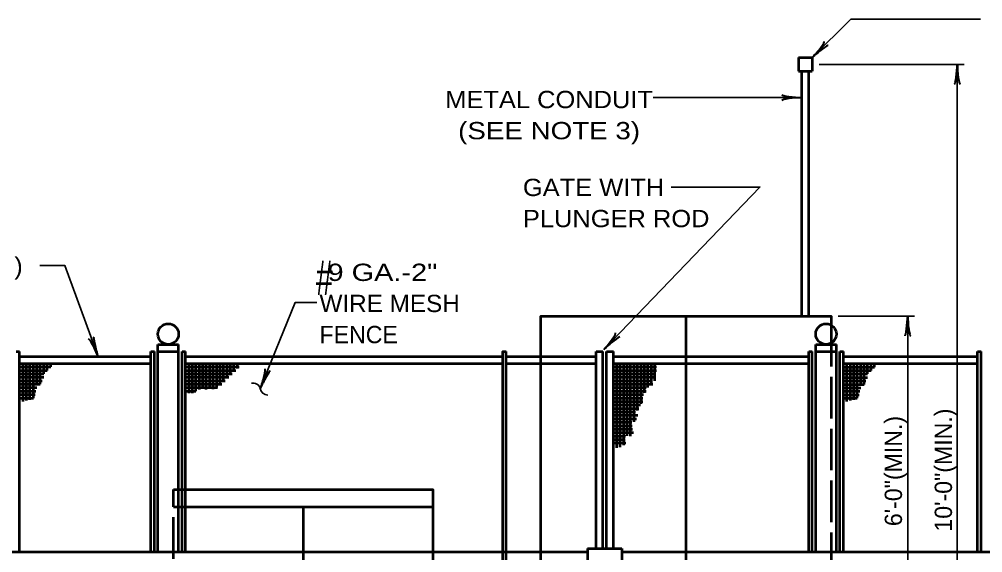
# Model space of a CAD drawing. Extents: x -1 to 679, y 0 to 440.
# Drawn here: x 122.8 to 262.1, y 140.7 to 217.9 of the extents above; entities that cross this region are included whole.
import ezdxf
from ezdxf.enums import TextEntityAlignment as Align

# ---------------------------------------------------------------- set-up
doc = ezdxf.new("R2010")
doc.units = 0
doc.linetypes.add('LONG_DASHED', pattern=[7.5, 6, -1.5])
doc.layers.add('1', color=7, linetype='Continuous', lineweight=53)

msp = doc.modelspace()

# ---------------------------------------------------------------- linework, layer by layer
at = {"layer": '1'}
for p, q in [((235.447, 212.358), (237.447, 212.358)), ((235.447, 212.358), (235.447, 210.358)), ((237.447, 212.358), (237.447, 210.358)), ((235.447, 210.358), (237.447, 210.358)), ((235.947, 174.962), (235.947, 210.358)), ((236.947, 174.962), (236.947, 210.358)), ((219.197, 174.962), (219.197, 109.858)), ((142.849, 170.858), (145.849, 170.858)), ((142.849, 140.858), (142.849, 170.858)), ((145.849, 140.858), (145.849, 170.858)), ((237.947, 170.858), (240.947, 170.858)), ((237.947, 140.858), (237.947, 170.858)), ((240.947, 140.858), (240.947, 170.858)), ((122.349, 169.858), (122.849, 169.858)), ((122.849, 140.858), (122.849, 169.858)), ((122.849, 169.108), (141.849, 169.108)), ((141.849, 169.858), (142.349, 169.858)), ((141.849, 140.858), (141.849, 169.858)), ((142.349, 140.858), (142.349, 169.858)), ((142.849, 169.858), (145.849, 169.858)), ((146.349, 169.858), (146.849, 169.858)), ((146.349, 140.858), (146.349, 169.858)), ((146.849, 140.858), (146.849, 169.858)), ((146.849, 169.108), (192.697, 169.108)), ((193.197, 108.858), (193.197, 169.858)), ((193.197, 169.108), (206.197, 169.108)), ((206.197, 169.858), (207.197, 169.858)), ((206.197, 141.358), (206.197, 169.858)), ((207.197, 141.358), (207.197, 169.858)), ((207.697, 169.858), (208.697, 169.858)), ((207.697, 141.358), (207.697, 169.858)), ((208.697, 141.358), (208.697, 169.858)), ((208.697, 169.108), (236.947, 169.108)), ((236.947, 169.858), (237.447, 169.858)), ((236.947, 140.858), (236.947, 169.858)), ((237.447, 140.858), (237.447, 169.858)), ((237.947, 169.858), (240.947, 169.858)), ((241.447, 169.858), (241.947, 169.858)), ((241.447, 140.858), (241.447, 169.858)), ((241.947, 140.858), (241.947, 169.858)), ((241.947, 169.108), (261.349, 169.108)), ((261.349, 140.858), (261.349, 169.858)), ((261.349, 169.858), (261.849, 169.858)), ((261.849, 140.858), (261.849, 169.858)), ((122.849, 168.108), (141.849, 168.108)), ((122.849, 167.608), (127.349, 167.608)), ((123.349, 162.608), (123.349, 168.108)), ((123.849, 162.758), (123.849, 168.108)), ((124.349, 162.858), (124.349, 168.108)), ((124.849, 163.108), (124.849, 168.108)), ((125.349, 165.108), (125.349, 168.108)), ((125.849, 165.108), (125.849, 168.108)), ((126.349, 166.608), (126.349, 168.108)), ((126.849, 167.108), (126.849, 168.108)), ((127.349, 167.608), (127.349, 168.108)), ((146.849, 168.108), (192.697, 168.108)), ((146.849, 167.608), (154.599, 167.608)), ((147.349, 163.79), (147.349, 168.108)), ((147.849, 163.817), (147.849, 168.108)), ((148.349, 164.108), (148.349, 168.108)), ((148.849, 164.332), (148.849, 168.108)), ((149.349, 164.413), (149.349, 168.108)), ((149.849, 164.359), (149.849, 168.108)), ((150.349, 164.413), (150.349, 168.108)), ((150.849, 164.386), (150.849, 168.108)), ((151.349, 164.608), (151.349, 168.108)), ((151.849, 165.108), (151.849, 168.108)), ((152.349, 165.608), (152.349, 168.108)), ((152.849, 165.93), (152.849, 168.108)), ((153.349, 166.498), (153.349, 168.108)), ((153.849, 167.013), (153.849, 168.108)), ((154.349, 167.358), (154.349, 168.108)), ((193.197, 168.108), (206.197, 168.108)), ((208.697, 168.108), (236.947, 168.108)), ((208.697, 167.608), (214.919, 167.608)), ((209.197, 155.917), (209.197, 168.108)), ((209.697, 156.002), (209.697, 168.108)), ((210.197, 156.282), (210.197, 168.108)), ((210.697, 157.655), (210.697, 168.108)), ((211.197, 157.612), (211.197, 168.108)), ((211.697, 159.652), (211.697, 168.108)), ((212.197, 161.305), (212.197, 168.108)), ((212.697, 162.271), (212.697, 168.108)), ((213.197, 163.881), (213.197, 168.108)), ((213.697, 164.632), (213.697, 168.108)), ((214.197, 164.911), (214.197, 168.108)), ((214.697, 165.608), (214.697, 168.108)), ((241.947, 168.108), (261.349, 168.108)), ((241.961, 167.585), (246.461, 167.585)), ((242.461, 162.585), (242.461, 168.085)), ((242.961, 162.735), (242.961, 168.085)), ((243.461, 162.835), (243.461, 168.085)), ((243.961, 163.085), (243.961, 168.085)), ((244.461, 165.085), (244.461, 168.085)), ((244.961, 165.085), (244.961, 168.085)), ((245.461, 166.585), (245.461, 168.085)), ((245.961, 167.085), (245.961, 168.085)), ((246.461, 167.585), (246.461, 168.085)), ((122.849, 167.108), (126.849, 167.108)), ((122.849, 166.608), (126.349, 166.608)), ((122.849, 166.108), (126.349, 166.108)), ((146.849, 167.108), (154.099, 167.108)), ((146.849, 166.608), (153.599, 166.608)), ((146.849, 166.108), (153.099, 166.108)), ((208.697, 167.108), (214.919, 167.108)), ((208.697, 166.608), (214.834, 166.608)), ((208.697, 166.108), (214.812, 166.108)), ((241.961, 167.085), (245.961, 167.085)), ((241.961, 166.585), (245.461, 166.585)), ((241.961, 166.085), (245.461, 166.085)), ((122.849, 165.608), (126.099, 165.608)), ((122.849, 165.108), (125.849, 165.108)), ((122.849, 164.608), (125.349, 164.608)), ((146.849, 165.608), (152.599, 165.608)), ((146.849, 165.108), (152.099, 165.108)), ((146.849, 164.608), (151.475, 164.608)), ((208.697, 165.608), (214.34, 165.608)), ((208.697, 165.108), (214.383, 165.108)), ((208.697, 164.608), (213.417, 164.608)), ((241.961, 165.585), (245.211, 165.585)), ((241.961, 165.085), (244.961, 165.085)), ((241.961, 164.585), (244.461, 164.585)), ((122.849, 164.108), (125.199, 164.108)), ((122.849, 163.608), (125.099, 163.608)), ((122.849, 163.108), (124.849, 163.108)), ((146.849, 164.108), (148.349, 164.108)), ((208.697, 164.108), (213.439, 164.108)), ((208.697, 163.608), (213.052, 163.608)), ((208.697, 163.108), (212.967, 163.108)), ((241.961, 164.085), (244.311, 164.085)), ((241.961, 163.585), (244.211, 163.585)), ((241.961, 163.085), (243.961, 163.085)), ((208.697, 162.608), (212.945, 162.608)), ((208.697, 162.108), (212.623, 162.108)), ((208.697, 161.608), (212.387, 161.608)), ((208.697, 161.108), (211.915, 161.108)), ((208.697, 160.608), (212.216, 160.608)), ((208.697, 160.108), (212.022, 160.108)), ((208.697, 159.608), (211.379, 159.608)), ((208.697, 159.108), (211.4, 159.108)), ((208.697, 158.608), (211.486, 158.608)), ((208.697, 158.108), (211.615, 158.108)), ((208.697, 157.608), (210.456, 157.608)), ((208.697, 157.108), (210.413, 157.108)), ((208.697, 156.608), (210.52, 156.608)), ((145.099, 147.358), (182.599, 147.358)), ((163.849, 147.358), (163.849, 109.858)), ((118.849, 140.858), (204.947, 140.858)), ((204.947, 141.358), (204.947, 138.858)), ((204.947, 141.358), (209.947, 141.358)), ((209.947, 141.358), (209.947, 138.858)), ((209.947, 140.858), (265.349, 140.858))]:
    msp.add_line(p, q, dxfattribs=at)
at = {"layer": '1', "lineweight": 35}
for p, q in [((259.422, 211.358), (238.447, 211.358)), ((258.422, 211.358), (258.422, 108.858)), ((235.947, 206.546), (214.435, 206.546)), ((252.255, 174.962), (241.197, 174.962)), ((251.255, 174.962), (251.255, 108.858))]:
    msp.add_line(p, q, dxfattribs=at)
at = {"layer": '1', "linetype": 'LONG_DASHED'}
for p, q in [((240.197, 173.657), (240.197, 109.858)), ((145.099, 109.858), (145.099, 149.858))]:
    msp.add_line(p, q, dxfattribs=at)
at = {"layer": '1', "lineweight": 35}
for points in [[(237.447, 212.358), (243.045, 217.88), (261.755, 217.88)], [(207.34, 170.143), (229.885, 193.611), (217.071, 193.611)], [(134.192, 169.108), (129.411, 182.261), (125.777, 182.261)], [(157.657, 164.505), (162.705, 176.923), (165.836, 176.923)]]:
    msp.add_lwpolyline(points, dxfattribs=at)
at = {"layer": '1'}
for points in [[(198.197, 109.858), (198.197, 174.962), (240.197, 174.962), (240.197, 173.657)], [(192.697, 108.858), (192.697, 169.858), (193.197, 169.858)], [(145.099, 149.858), (182.599, 149.858), (182.599, 109.858)]]:
    msp.add_lwpolyline(points, dxfattribs=at)
for centre in [(144.349, 172.358), (239.447, 172.358)]:
    msp.add_circle(centre, 1.5, dxfattribs=at)
at = {"layer": '1', "lineweight": 35}
for centre, start, end in [((156.621, 164.169), 17.97301, 102.52429), ((158.74, 164.616), 185.89086, 270.44213)]:
    msp.add_arc(centre, 1.089, start, end, dxfattribs=at)
at = {"layer": '1', "lineweight": 40}
for centre, major_axis, ratio, start_param, end_param in [((238.03, 213.321), (-1.162, -1.365), 0.122415, 0.8963533, 3.1415927), ((238.03, 213.321), (-1.162, -1.365), 0.122415, 0.8963533, 3.1415927), ((238.393, 212.994), (1.374, 1.108), 0.07063, 6.2823074, 8.5597026), ((238.393, 212.994), (1.374, 1.108), 0.07063, 6.2823074, 8.5597026), ((258.211, 210.237), (0.176, 1.756), 0.07063, 3.1407148, 5.41811), ((258.211, 210.237), (0.176, 1.756), 0.07063, 3.1407148, 5.41811), ((258.698, 210.266), (-0.156, 1.786), 0.122415, 0.8963533, 3.1415927), ((258.698, 210.266), (-0.156, 1.786), 0.122415, 0.8963533, 3.1415927), ((234.856, 206.27), (1.786, 0.156), 0.122415, 0.8963533, 3.1415927), ((234.856, 206.27), (1.786, 0.156), 0.122415, 0.8963533, 3.1415927), ((234.826, 206.758), (1.756, -0.176), 0.07063, 3.1407148, 5.41811), ((234.826, 206.758), (1.756, -0.176), 0.07063, 3.1407148, 5.41811), ((251.043, 173.842), (0.176, 1.756), 0.07063, 3.1407148, 5.41811), ((251.043, 173.842), (0.176, 1.756), 0.07063, 3.1407148, 5.41811), ((251.531, 173.871), (-0.156, 1.786), 0.122415, 0.8963533, 3.1415927), ((251.531, 173.871), (-0.156, 1.786), 0.122415, 0.8963533, 3.1415927), ((133.56, 170.039), (0.757, -1.625), 0.122415, 0.8963533, 3.1415927), ((133.56, 170.039), (0.757, -1.625), 0.122415, 0.8963533, 3.1415927), ((134.008, 170.233), (-0.435, 1.711), 0.07063, 6.2823074, 8.5597026), ((134.008, 170.233), (-0.435, 1.711), 0.07063, 6.2823074, 8.5597026), ((207.897, 171.121), (-1.124, -1.396), 0.122415, 0.8963533, 3.1415927), ((207.897, 171.121), (-1.124, -1.396), 0.122415, 0.8963533, 3.1415927), ((208.269, 170.804), (-1.343, -1.145), 0.07063, 3.1407148, 5.41811), ((208.269, 170.804), (-1.343, -1.145), 0.07063, 3.1407148, 5.41811), ((157.812, 165.62), (-0.528, -1.713), 0.122415, 0.8963533, 3.1415927), ((158.275, 165.463), (0.824, 1.561), 0.07063, 6.2823074, 8.5597026)]:
    msp.add_ellipse(centre, major_axis=major_axis, ratio=ratio, start_param=start_param, end_param=end_param, dxfattribs=at)

# ---------------------------------------------------------------- texts
at = {"layer": '1'}
for s, height, width, p in [('METAL CONDUIT', 2.5, 1.1, (199.407, 205.027)), ('(SEE NOTE 3)', 2.5, 1.2, (199.407, 200.527)), ('1 5/8" 0 TOP RAIL (TYP.)', 2.5, 1.1, (102.322, 180.97)), ('#', 5, 0.65, (166.911, 177.995))]:
    msp.add_text(s, height=height, dxfattribs=dict(at, width=width)).set_placement(p, align=Align.CENTER)
for s, width, p in [('GATE WITH', 1.1, (195.622, 192.313)), ('PLUNGER ROD', 1.1, (195.622, 187.813)), (' 9 GA.-2"', 1.25, (166.213, 180.036)), ('WIRE MESH', 1.05, (166.213, 175.536))]:
    msp.add_text(s, height=2.5, dxfattribs=dict(at, width=width)).set_placement(p)
msp.add_text('FENCE', height=2.5, dxfattribs=at).set_placement((166.213, 171.036))
for s, p in [('6\'-0"(MIN.)', (250.427, 152.55)), ('10\'-0"(MIN.)', (257.654, 152.686))]:
    msp.add_text(s, height=2.5, rotation=90, dxfattribs=at).set_placement(p, align=Align.CENTER)

doc.saveas('drawing.dxf')
